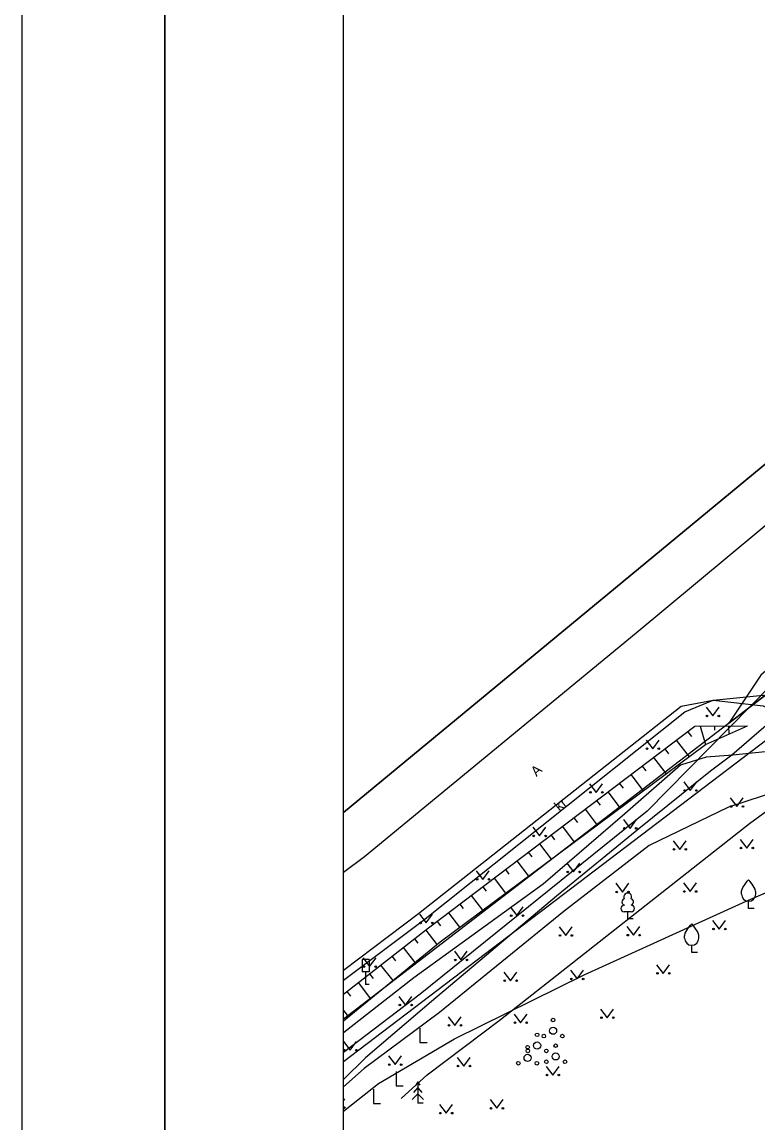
# Model space of a CAD drawing. Extents: x 648017 to 648227, y 6561313 to 6561610.
# Drawn here: x 648016.8 to 648068.3, y 6561381.6 to 6561458.6 of the extents above; entities that cross this region are included whole.
import ezdxf

# ---------------------------------------------------------------- set-up
doc = ezdxf.new("R2010")
doc.units = 0
for name, color, linetype in [('HALJASTUS', 7, 'Continuous'), ('KASUTUSALA', 7, 'Continuous'), ('LIIKLUS', 7, 'Continuous'), ('PIIR', 7, 'Continuous'), ('PR_SIDE', 7, 'Continuous'), ('PUU', 7, 'Continuous'), ('RELJEEF', 7, 'Continuous'), ('SITRASS', 7, 'Continuous'), ('TEE', 7, 'Continuous'), ('VORMISTUS', 7, 'Continuous')]:
    doc.layers.add(name, color=color, linetype=linetype)

msp = doc.modelspace()

# ---------------------------------------------------------------- linework, layer by layer
at = {"layer": 'HALJASTUS'}
for p, q in [((648064.662, 6561410.696), (648065.126, 6561410.09)), ((648065.126, 6561410.09), (648065.571, 6561410.696)), ((648060.458, 6561408.405), (648060.921, 6561407.798)), ((648060.921, 6561407.798), (648061.367, 6561408.405)), ((648056.503, 6561405.346), (648056.966, 6561404.74)), ((648056.966, 6561404.74), (648057.411, 6561405.346)), ((648063.092, 6561405.479), (648063.555, 6561404.872)), ((648063.555, 6561404.872), (648064.001, 6561405.479)), ((648066.354, 6561404.359), (648066.817, 6561403.752)), ((648066.817, 6561403.752), (648067.263, 6561404.359)), ((648058.875, 6561402.832), (648059.339, 6561402.225)), ((648059.339, 6561402.225), (648059.784, 6561402.832)), ((648052.536, 6561402.302), (648052.999, 6561401.696)), ((648052.999, 6561401.696), (648053.445, 6561402.302)), ((648062.352, 6561401.361), (648062.815, 6561400.754)), ((648062.815, 6561400.754), (648063.261, 6561401.361)), ((648067.041, 6561401.455), (648067.504, 6561400.848)), ((648067.504, 6561400.848), (648067.95, 6561401.455)), ((648054.916, 6561399.778), (648055.379, 6561399.172)), ((648055.379, 6561399.172), (648055.825, 6561399.778)), ((648048.569, 6561399.259), (648049.033, 6561398.652)), ((648049.033, 6561398.652), (648049.478, 6561399.259)), ((648058.34, 6561398.377), (648058.804, 6561397.77)), ((648058.804, 6561397.77), (648059.249, 6561398.377)), ((648063.073, 6561398.413), (648063.536, 6561397.806)), ((648063.536, 6561397.806), (648063.982, 6561398.413)), ((648050.956, 6561396.725), (648051.42, 6561396.118)), ((648051.42, 6561396.118), (648051.865, 6561396.725)), ((648044.604, 6561396.213), (648045.067, 6561395.606)), ((648045.067, 6561395.606), (648045.513, 6561396.213)), ((648065.116, 6561395.786), (648065.58, 6561395.179)), ((648065.58, 6561395.179), (648066.025, 6561395.786)), ((648054.375, 6561395.333), (648054.838, 6561394.726)), ((648054.838, 6561394.726), (648055.284, 6561395.333)), ((648059.118, 6561395.353), (648059.582, 6561394.747)), ((648059.582, 6561394.747), (648060.027, 6561395.353)), ((648047.038, 6561393.62), (648047.502, 6561393.013)), ((648047.502, 6561393.013), (648047.947, 6561393.62)), ((648040.646, 6561393.157), (648041.11, 6561392.55)), ((648041.11, 6561392.55), (648041.555, 6561393.157)), ((648061.195, 6561392.683), (648061.659, 6561392.076)), ((648061.659, 6561392.076), (648062.104, 6561392.683)), ((648050.503, 6561392.17), (648050.966, 6561391.563)), ((648050.966, 6561391.563), (648051.412, 6561392.17)), ((648055.167, 6561392.29), (648055.63, 6561391.683)), ((648055.63, 6561391.683), (648056.076, 6561392.29)), ((648043.159, 6561390.465), (648043.622, 6561389.859)), ((648043.622, 6561389.859), (648044.068, 6561390.465)), ((648057.275, 6561389.58), (648057.738, 6561388.974)), ((648057.738, 6561388.974), (648058.184, 6561389.58)), ((648046.606, 6561389.04), (648047.069, 6561388.433)), ((648047.069, 6561388.433), (648047.515, 6561389.04)), ((648051.215, 6561389.226), (648051.679, 6561388.619)), ((648051.679, 6561388.619), (648052.124, 6561389.226)), ((648044.626, 6561388.245), (648044.626, 6561387.245)), ((648039.279, 6561387.311), (648039.742, 6561386.705)), ((648039.742, 6561386.705), (648040.188, 6561387.311)), ((648044.626, 6561387.245), (648045.126, 6561387.245)), ((648042.423, 6561386.301), (648042.886, 6561385.694)), ((648042.886, 6561385.694), (648043.332, 6561386.301)), ((648047.237, 6561386.198), (648047.7, 6561385.591)), ((648047.7, 6561385.591), (648048.146, 6561386.198)), ((648053.461, 6561385.568), (648053.925, 6561384.961)), ((648053.925, 6561384.961), (648054.37, 6561385.568)), ((648042.964, 6561385.212), (648042.964, 6561384.212)), ((648042.964, 6561384.212), (648043.464, 6561384.212)), ((648039.275, 6561383.167), (648039.363, 6561383.287)), ((648041.376, 6561383.971), (648041.376, 6561382.971)), ((648049.545, 6561383.241), (648050.008, 6561382.634)), ((648050.008, 6561382.634), (648050.454, 6561383.241)), ((648041.376, 6561382.971), (648041.876, 6561382.971)), ((648045.992, 6561382.902), (648046.456, 6561382.295)), ((648046.456, 6561382.295), (648046.901, 6561382.902))]:
    msp.add_line(p, q, dxfattribs=at)
msp.add_lwpolyline([(648043.318, 6561383.328), (648045.146, 6561384.984), (648050.259, 6561388.844), (648067.703, 6561402.558), (648071.941, 6561405.665), (648074.773, 6561403.529), (648074.941, 6561402.506)], dxfattribs=at)
for centre in [(648064.725, 6561410.09), (648065.554, 6561410.09), (648060.52, 6561407.798), (648061.349, 6561407.798), (648063.154, 6561404.872), (648063.983, 6561404.872), (648056.565, 6561404.74), (648057.394, 6561404.74), (648066.416, 6561403.752), (648067.245, 6561403.752), (648052.598, 6561401.696), (648053.427, 6561401.696), (648058.938, 6561402.225), (648059.766, 6561402.225), (648062.414, 6561400.754), (648063.243, 6561400.754), (648067.103, 6561400.848), (648067.932, 6561400.848), (648048.632, 6561398.652), (648049.46, 6561398.652), (648054.978, 6561399.172), (648055.807, 6561399.172), (648058.403, 6561397.77), (648059.231, 6561397.77), (648063.135, 6561397.806), (648063.964, 6561397.806), (648044.666, 6561395.606), (648045.495, 6561395.606), (648051.019, 6561396.118), (648051.847, 6561396.118), (648059.181, 6561394.747), (648060.009, 6561394.747), (648065.179, 6561395.179), (648066.007, 6561395.179), (648054.437, 6561394.726), (648055.266, 6561394.726), (648040.709, 6561392.55), (648041.538, 6561392.55), (648047.101, 6561393.013), (648047.929, 6561393.013), (648055.229, 6561391.683), (648056.058, 6561391.683), (648061.258, 6561392.076), (648062.086, 6561392.076), (648050.565, 6561391.563), (648051.394, 6561391.563), (648043.221, 6561389.859), (648044.05, 6561389.859), (648051.278, 6561388.619), (648052.106, 6561388.619), (648057.337, 6561388.974), (648058.166, 6561388.974), (648046.668, 6561388.433), (648047.497, 6561388.433), (648039.341, 6561386.705), (648040.17, 6561386.705), (648042.485, 6561385.694), (648043.314, 6561385.694), (648047.299, 6561385.591), (648048.128, 6561385.591), (648053.524, 6561384.961), (648054.352, 6561384.961), (648039.345, 6561382.68), (648049.607, 6561382.634), (648050.436, 6561382.634), (648046.055, 6561382.295), (648046.884, 6561382.295)]:
    msp.add_circle(centre, 0.055, dxfattribs=at)
at = {"layer": 'KASUTUSALA'}
msp.add_lwpolyline([(648069.33, 6561411.95), (648079.41, 6561420.36), (648130.76, 6561463.29), (648148.46, 6561478.24), (648152.687, 6561481.861), (648163.17, 6561490.84), (648165.149, 6561492.835), (648178.343, 6561506.54), (648179.793, 6561507.812), (648180.15, 6561508.27), (648181.07, 6561509.57), (648179.717, 6561510.405), (648176.961, 6561507.989), (648163.749, 6561494.265), (648163.1, 6561493.666), (648154.204, 6561485.901), (648141.111, 6561474.192), (648118.068, 6561454.823), (648078.72, 6561421.738), (648068.502, 6561412.945), (648066.261, 6561409.593)], close=True, dxfattribs=at)
at = {"layer": 'LIIKLUS'}
for p, q in [((648040.575, 6561393.037), (648040.575, 6561392.187)), ((648041.075, 6561393.037), (648040.575, 6561393.037)), ((648041.075, 6561393.037), (648041.075, 6561392.187)), ((648041.075, 6561392.187), (648040.575, 6561392.187)), ((648040.825, 6561392.187), (648040.825, 6561391.287)), ((648041.075, 6561391.287), (648040.825, 6561391.287))]:
    msp.add_line(p, q, dxfattribs=at)
at = {"layer": 'PIIR'}
for points in [[(648199.342, 6561559.885), (648199.07, 6561558.2), (648195.16, 6561543.45), (648190.37, 6561530.46), (648184.89, 6561519.28), (648179.37, 6561510.62), (648181.07, 6561509.57), (648180.15, 6561508.27), (648175.42, 6561502.2), (648170.88, 6561497.65), (648163.17, 6561490.84), (648148.46, 6561478.24), (648130.76, 6561463.29), (648079.41, 6561420.36), (648069.33, 6561411.95), (648039.275, 6561388.867)], [(648148.783, 6561559.885), (648090, 6561513.15), (648123.09, 6561472.56), (648039.275, 6561403.329)], [(648039.275, 6561403.329), (648123.09, 6561472.56), (648162.4, 6561506.57), (648170.84, 6561515.84), (648172.53, 6561514.72), (648177.65, 6561522.71), (648182.83, 6561533.2), (648187.47, 6561545.71), (648191.21, 6561559.62), (648191.239, 6561559.885)], [(648039.275, 6561385.901), (648070.56, 6561409.69), (648074.96, 6561406.62), (648083.938, 6561349.885)]]:
    msp.add_lwpolyline(points, dxfattribs=at)
at = {"layer": 'PR_SIDE'}
msp.add_lwpolyline([(648199.292, 6561518.475), (648197.479, 6561519.53), (648193.724, 6561520.506), (648191.997, 6561519.841), (648177.652, 6561507.265), (648164.449, 6561493.55), (648163.768, 6561492.922), (648154.867, 6561485.151), (648141.766, 6561473.436), (648118.712, 6561454.058), (648079.383, 6561420.989), (648069.186, 6561412.213), (648060.526, 6561403.421), (648044.656, 6561390.621), (648039.275, 6561386.529)], dxfattribs=at)
at = {"layer": 'PUU'}
for p, q in [((648067.636, 6561396.624), (648067.636, 6561397.124)), ((648059.415, 6561396.375), (648058.935, 6561396.375)), ((648059.175, 6561395.9), (648059.175, 6561396.375)), ((648068.036, 6561396.624), (648067.636, 6561396.624)), ((648059.555, 6561395.9), (648059.175, 6561395.9)), ((648063.655, 6561393.541), (648063.655, 6561394.041)), ((648064.055, 6561393.541), (648063.655, 6561393.541)), ((648044.487, 6561384.097), (648044.187, 6561383.747)), ((648044.487, 6561384.497), (648044.337, 6561384.247)), ((648044.637, 6561384.247), (648044.487, 6561384.497)), ((648044.487, 6561384.497), (648044.487, 6561382.997)), ((648044.787, 6561383.747), (648044.487, 6561384.097)), ((648044.487, 6561383.647), (648044.087, 6561383.247)), ((648044.887, 6561383.247), (648044.487, 6561383.647)), ((648044.847, 6561382.997), (648044.487, 6561382.997))]:
    msp.add_line(p, q, dxfattribs=at)
for points in [[(648067.136, 6561397.624), (648067.136, 6561397.774), (648067.146, 6561397.839), (648067.181, 6561397.969), (648067.241, 6561398.089), (648067.386, 6561398.324), (648067.546, 6561398.529), (648067.636, 6561398.624)], [(648068.136, 6561397.624), (648068.136, 6561397.774), (648068.126, 6561397.839), (648068.091, 6561397.969), (648068.031, 6561398.089), (648067.886, 6561398.324), (648067.726, 6561398.529), (648067.636, 6561398.624)], [(648063.155, 6561394.541), (648063.155, 6561394.691), (648063.165, 6561394.756), (648063.2, 6561394.886), (648063.26, 6561395.006), (648063.405, 6561395.241), (648063.565, 6561395.446), (648063.655, 6561395.541)], [(648064.155, 6561394.541), (648064.155, 6561394.691), (648064.145, 6561394.756), (648064.11, 6561394.886), (648064.05, 6561395.006), (648063.905, 6561395.241), (648063.745, 6561395.446), (648063.655, 6561395.541)]]:
    msp.add_lwpolyline(points, dxfattribs=at)
for centre, radius in [((648053.95, 6561388.811), 0.125), ((648052.831, 6561387.777), 0.125), ((648053.95, 6561388.061), 0.25), ((648052.831, 6561387.027), 0.25), ((648053.3, 6561387.686), 0.125), ((648054.129, 6561387.016), 0.125), ((648054.6, 6561387.686), 0.125), ((648052.166, 6561386.162), 0.25), ((648052.166, 6561386.912), 0.125), ((648052.181, 6561386.652), 0.125), ((648053.481, 6561386.652), 0.125), ((648054.129, 6561386.266), 0.25), ((648051.516, 6561385.787), 0.125), ((648052.816, 6561385.787), 0.125), ((648053.479, 6561385.891), 0.125), ((648054.779, 6561385.891), 0.125)]:
    msp.add_circle(centre, radius, dxfattribs=at)
for centre, radius, start, end in [((648059.005, 6561397.073), 0.233, 109.02174, 253.14154), ((648059.175, 6561397.42), 0.277, 332.5799, 207.4201), ((648059.345, 6561397.073), 0.233, 286.85082, 70.98591), ((648067.636, 6561397.624), 0.5, 180, 0), ((648058.938, 6561396.613), 0.238, 90.0016, 269.3953), ((648059.413, 6561396.613), 0.238, 270.6047, 89.9984), ((648063.655, 6561394.541), 0.5, 180, 0)]:
    msp.add_arc(centre, radius, start, end, dxfattribs=at)
at = {"layer": 'RELJEEF'}
for p, q in [((648063.368, 6561409.003), (648063.638, 6561408.648)), ((648064.24, 6561409.386), (648064.62, 6561408.08)), ((648065.24, 6561409.393), (648065.242, 6561409.084)), ((648066.24, 6561409.399), (648066.244, 6561408.816)), ((648067.24, 6561409.405), (648067.24, 6561409.364)), ((648062.571, 6561408.399), (648063.464, 6561407.222)), ((648060.977, 6561407.191), (648061.858, 6561406.03)), ((648061.774, 6561407.795), (648062.04, 6561407.444)), ((648060.18, 6561406.587), (648060.442, 6561406.241)), ((648059.383, 6561405.983), (648060.252, 6561404.838)), ((648058.586, 6561405.379), (648058.845, 6561405.038)), ((648056.992, 6561404.171), (648057.247, 6561403.835)), ((648057.789, 6561404.775), (648058.645, 6561403.646)), ((648056.195, 6561403.568), (648057.039, 6561402.454)), ((648055.398, 6561402.964), (648055.65, 6561402.632)), ((648053.804, 6561401.756), (648054.052, 6561401.429)), ((648054.601, 6561402.36), (648055.433, 6561401.262)), ((648053.007, 6561401.152), (648053.827, 6561400.07)), ((648052.21, 6561400.548), (648052.454, 6561400.225)), ((648051.413, 6561399.944), (648052.221, 6561398.878)), ((648049.819, 6561398.736), (648050.615, 6561397.686)), ((648050.616, 6561399.34), (648050.857, 6561399.022)), ((648049.022, 6561398.132), (648049.259, 6561397.819)), ((648048.225, 6561397.528), (648049.009, 6561396.494)), ((648047.428, 6561396.924), (648047.662, 6561396.616)), ((648045.834, 6561395.716), (648046.064, 6561395.413)), ((648046.631, 6561396.32), (648047.403, 6561395.302)), ((648045.039, 6561395.109), (648045.817, 6561394.108)), ((648044.249, 6561394.496), (648044.487, 6561394.189)), ((648042.67, 6561393.269), (648042.917, 6561392.95)), ((648043.46, 6561393.883), (648044.269, 6561392.84)), ((648041.88, 6561392.656), (648042.722, 6561391.572)), ((648041.09, 6561392.042), (648041.348, 6561391.711)), ((648040.301, 6561391.429), (648041.174, 6561390.304)), ((648039.511, 6561390.815), (648039.778, 6561390.472)), ((648039.275, 6561389.489), (648039.626, 6561389.037))]:
    msp.add_line(p, q, dxfattribs=at)
for points in [[(648039.275, 6561388.749), (648046.037, 6561394.288), (648064.62, 6561408.08), (648067.549, 6561409.407)], [(648039.275, 6561390.632), (648045.232, 6561395.26), (648063.87, 6561409.384), (648067.549, 6561409.407)]]:
    msp.add_lwpolyline(points, dxfattribs=at)
at = {"layer": 'SITRASS'}
for points in [[(648086.748, 6561413.866), (648081.478, 6561412.832), (648077.7, 6561412.27), (648071.841, 6561410.71), (648068.859, 6561409.424), (648066.455, 6561407.341), (648064.964, 6561406.234), (648059.947, 6561402.189), (648054.198, 6561397.472), (648045.438, 6561390.103), (648040.817, 6561386.172), (648039.275, 6561384.639)], [(648082.302, 6561407.901), (648079.4, 6561407.797), (648075.375, 6561407.837), (648073.437, 6561407.588), (648069.464, 6561407.638), (648066.527, 6561407.339), (648064.664, 6561407.213), (648062.936, 6561406.667), (648062.868, 6561406.65), (648058.98, 6561403.232), (648053.259, 6561398.322), (648044.21, 6561391.764), (648039.275, 6561387.907)], [(648082.387, 6561405.903), (648080.358, 6561405.942), (648075.684, 6561405.704), (648072.377, 6561405.712), (648066.229, 6561403.712), (648060.686, 6561401.017), (648054.729, 6561396.422), (648045.992, 6561389.333), (648040.723, 6561385.425), (648039.275, 6561384.147)], [(648039.275, 6561382.438), (648041.726, 6561384.362), (648047.054, 6561387.491), (648056.131, 6561391.983), (648067.468, 6561397.134), (648075.572, 6561400.639), (648081.037, 6561403.206), (648083.002, 6561403.37)]]:
    msp.add_lwpolyline(points, dxfattribs=at)
at = {"layer": 'TEE'}
for points in [[(648123.326, 6561469.198), (648122.878, 6561468.198), (648118.137, 6561464.111), (648105.565, 6561453.509), (648088.284, 6561439.263), (648074.857, 6561428.431), (648059.756, 6561415.877), (648040.748, 6561400.235), (648039.275, 6561399.135)], [(648039.275, 6561392.3), (648044.53, 6561396.273), (648062.926, 6561410.785), (648065.147, 6561411.205), (648068.657, 6561411.551), (648073.418, 6561409.482), (648076.263, 6561406.029), (648077.76, 6561401.016)], [(648039.275, 6561391.609), (648044.873, 6561395.803), (648063.173, 6561410.375), (648065.147, 6561411.205), (648068.648, 6561410.798), (648072.831, 6561408.913), (648076.263, 6561406.029)]]:
    msp.add_lwpolyline(points, dxfattribs=at)
at = {"layer": 'VORMISTUS'}
for points in [[(648016.775, 6561609.885), (648226.775, 6561609.885), (648226.775, 6561312.885), (648016.775, 6561312.885)], [(648026.775, 6561323.885), (648216.775, 6561323.885), (648216.775, 6561598.885), (648026.775, 6561598.885)], [(648026.775, 6561598.885), (648216.775, 6561598.885), (648216.775, 6561323.885), (648026.775, 6561323.885)], [(648204.275, 6561349.885), (648039.275, 6561349.885), (648039.275, 6561559.885), (648204.275, 6561559.885)]]:
    msp.add_lwpolyline(points, close=True, dxfattribs=at)

# ---------------------------------------------------------------- texts
at = {"layer": 'TEE'}
for s, rotation, p in [('A', 43.53297, (648052.791, 6561405.811)), ('kr', 40.02175, (648054.393, 6561403.389))]:
    msp.add_text(s, height=0.7, rotation=rotation, dxfattribs=at).set_placement(p)

doc.saveas('drawing.dxf')
